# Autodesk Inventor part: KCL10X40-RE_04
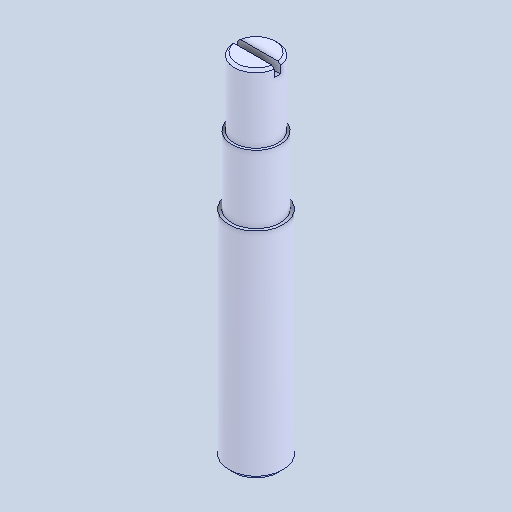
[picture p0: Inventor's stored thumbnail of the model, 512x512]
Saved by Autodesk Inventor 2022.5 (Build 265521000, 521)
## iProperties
Created: 2024-08
Part Number: KCL10X40-RE_04
Material: 一般
Document SubType Name: Modeling
Designer: ImaoCorp
Density: 1 g/cm^3
Appearance: 既定
Author: ImaoCorp
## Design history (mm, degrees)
feature "KCL10X40-RE_04"
node "ソリッド1"
